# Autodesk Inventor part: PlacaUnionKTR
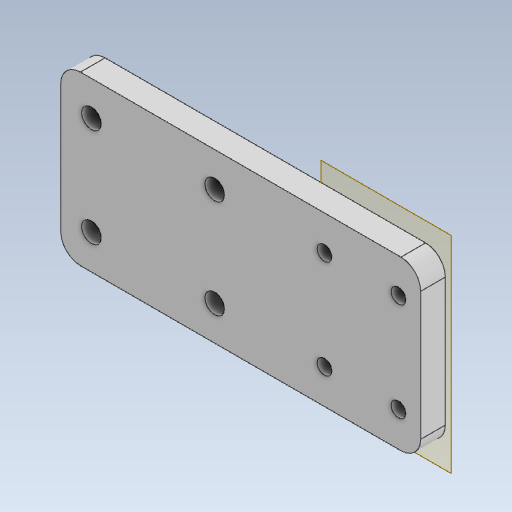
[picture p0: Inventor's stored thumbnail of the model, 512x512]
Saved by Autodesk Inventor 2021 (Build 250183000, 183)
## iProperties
Created: 2021-02
Part Number: PlacaUnionKTR
Material: Genérico
Document SubType Name: Modeling
Designer: ATOUZA
Density: 1 g/cm^3
Appearance: Valor por defecto
Author: ATOUZA
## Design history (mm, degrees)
node "Plano de trabajo1"
sketch "Boceto1"
  geometry: L1 (-24, 0)-(0, 0) reference; L2 (-24, 0)-(-24, -38) reference; L3 (0, -38)-(-24, -38) reference; L4 (-45.275, 1.9)-(-48.575, 1.9) reference; L5 (-48.575, 1.9)-(-48.575, -56.5) reference; L6 (-45.275, -56.5)-(-48.575, -56.5) reference; L7 (-45.275, 1.9)-(-45.275, -56.5) reference; L8 (-59.975, 1.9)-(-63.275, 1.9) reference; L9 (-63.275, 1.9)-(-63.275, -56.5) reference; L10 (-59.975, -56.5)-(-63.275, -56.5) reference; L11 (-59.975, 1.9)-(-59.975, -56.5) reference; L12 (-48.575, 1.9)-(-59.975, 1.9) reference; L13 (-59.975, 1.9)-(-59.975, -56.5) reference; L14 (-48.575, -56.5)-(-59.975, -56.5) reference; L15 (-48.575, 1.9)-(-48.575, -56.5) reference; L16 (-63.275, -41)-(-45.275, -41) reference; L17 (0, -2)-(-73, -2); L18 (-73, -2)-(-73, -36); L19 (-73, -36)-(0, -36); L20 (0, -2)-(0, -36); L21 (-54.275, 1.9)-(-54.275, -36); L22 (-54.275, -9)-(-41.775, -9); L23 (-54.275, -19)-(-45.275, -19); C1 r 1.5 at (-4.5, -29) reference; C2 r 1.5 at (-4.5, -9) reference; C3 r 1.5 at (-19.5, -29) reference; C4 r 1.5 at (-19.5, -9) reference; C5 r 1.5 at (-19.5, -9); C6 r 1.5 at (-4.5, -9); C7 r 1.5 at (-19.5, -29); C8 r 1.5 at (-4.5, -29); C9 r 2 at (-41.775, -9); C10 r 2 at (-66.775, -9); C11 r 2 at (-41.775, -29); C12 r 2 at (-66.775, -29)
  constraints: 14 end point, 8 centre point, 5 coincident, 4 concentric, 4 perpendicular, 4 point on line, 3 symmetric about line, 1 horizontal, 1 midpoint, 1 parallel, 1 vertical, 3 other
  dimensions: "d0" = 12.5 distance of L22.start L22.end; "d1" = 4 diameter of C9; "d2" = 34 distance of L17.end L18.end; "d3" = 73 distance of L18.end L19.end; "d4" = 73 distance from line of L18 L1.end; "d5" = 7 distance from line of L17 C4.centre; "d6" = 7 distance from line of L19 C3.centre (derived); "d7" = 20 distance of C3.centre C4.centre (derived); "d8" = 7 distance from line of L17 L22.end; "d9" = 20 distance of C11.centre C9.centre
extrude "Extrusión1" new body sketch "Boceto1" distance "d10" = 5; taper "d11" = 0 deg
fillet "Empalme1" dims "d12" = 4
node "Sólido1"
node "Referencia2"
node "Referencia3"
node "Referencia4"
node "Referencia5"
